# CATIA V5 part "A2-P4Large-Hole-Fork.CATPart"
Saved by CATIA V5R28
Part number: Large-Hole-Fork
Revision: ANY
Definition: UNKNOWN
Nomenclature: Large-Hole-Fork
Source: Unknown
Bounding box of the stored display mesh (mm): x 0 to 142, y -36 to 36, z -36 to 36
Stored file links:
  E:\TP Catia - Documents\Additional Exercise\Contrôle\Problem-3-Section-J\A2-P4Large-Hole-Fork.CATPart
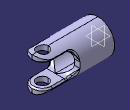
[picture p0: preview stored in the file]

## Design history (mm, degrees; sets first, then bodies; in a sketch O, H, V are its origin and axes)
Body1 "Imported1" (main body)
  Solid1: solid without history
